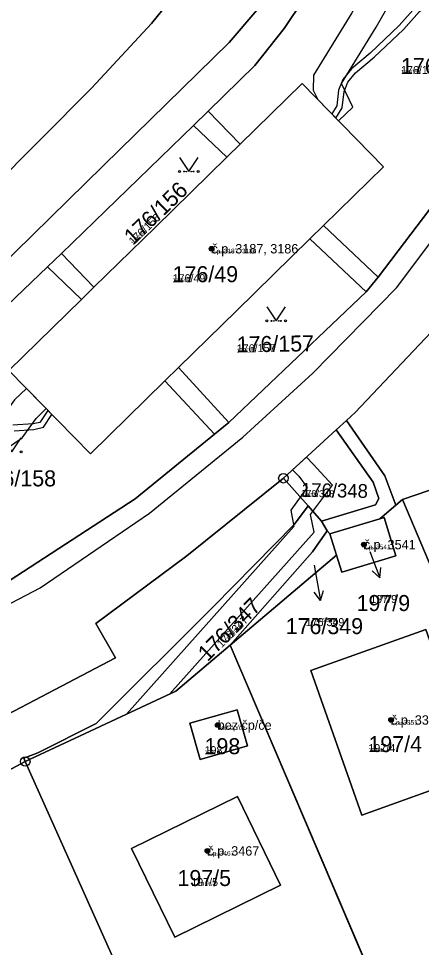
# Model space of a CAD drawing. Extents: x -759873 to -758487, y -975024 to -973516.
# Drawn here: x -759216.9 to -759174.1, y -974880.1 to -974781.5 of the extents above; entities that cross this region are included whole.
import ezdxf

# ---------------------------------------------------------------- set-up
doc = ezdxf.new("R2010")
doc.units = 0
for name, color, linetype in [('KAT_02_hranice parcel', 7, 'Continuous'), ('KAT_03_1000_st čísla parcelní', 7, 'Continuous'), ('KAT_03_1000_čísla parcelní', 7, 'Continuous'), ('KAT_03_1000_čísla popisná', 7, 'Continuous'), ('KAT_03_250_st čísla parcelní', 7, 'Continuous'), ('KAT_03_250_čísla parcelní', 7, 'Continuous'), ('KAT_03_250_čísla popisná', 7, 'Continuous'), ('KAT_03_500_st čísla parcelní', 7, 'Continuous'), ('KAT_03_500_čísla parcelní', 7, 'Continuous'), ('KAT_03_500_čísla popisná', 7, 'Continuous'), ('KAT_04_vnitřní kresba', 7, 'Continuous'), ('KAT_05_1000_značky kultur', 7, 'Continuous'), ('KAT_05_250_značky kultur', 7, 'Continuous'), ('KAT_05_500_značky kultur', 7, 'Continuous'), ('KAT_07_1000_značky budov', 7, 'Continuous'), ('KAT_07_250_značky budov', 7, 'Continuous'), ('KAT_07_500_značky budov', 7, 'Continuous'), ('KAT_10_věcná břemena', 7, 'Continuous'), ('KAT_11_značky bodu BP', 7, 'Continuous'), ('KAT_12_pomocná šipka', 7, 'Continuous'), ('KAT_14_plocha_budovy', 7, 'Continuous'), ('KAT_14_plocha_pozemek', 7, 'Continuous')]:
    doc.layers.add(name, color=color, linetype=linetype)

msp = doc.modelspace()

# ---------------------------------------------------------------- linework, layer by layer
at = {"layer": 'KAT_02_hranice parcel'}
for p, q in [((-759196.78, -974791.27), (-759198.31, -974792.79)), ((-759198.31, -974792.79), (-759212.35, -974806.39)), ((-759212.35, -974806.39), (-759213.82, -974807.81)), ((-759179.98, -974810.45), (-759178.71, -974808.89)), ((-759194.56, -974824.34), (-759179.98, -974810.45)), ((-759148.15, -974822.94), (-759176.11, -974832.51)), ((-759196.1, -974825.59), (-759194.56, -974824.34)), ((-759183.17, -974825.13), (-759182.08, -974824.14)), ((-759188.78, -974830.26), (-759183.17, -974825.13)), ((-759186.16, -974833.19), (-759188.78, -974830.26)), ((-759184.73, -974834.81), (-759186.16, -974833.19)), ((-759176.83, -974833.12), (-759178.53, -974834.55)), ((-759176.11, -974832.51), (-759176.83, -974833.12)), ((-759159.23, -974872.41), (-759176.11, -974832.51)), ((-759183.12, -974838.42), (-759194.44, -974847.98)), ((-759167.42, -974911.17), (-759194.44, -974847.98)), ((-759216.19, -974860.33), (-759226.6, -974865.92)), ((-759189.72, -974919.43), (-759216.19, -974860.33))]:
    msp.add_line(p, q, dxfattribs=at)
for points in [[(-759182.08, -974824.14), (-759181.15, -974823.29), (-759171.83, -974813.43), (-759165.02, -974804.41), (-759157.43, -974793.66), (-759153.11, -974796.03), (-759143.25, -974777.05), (-759139.01, -974766.6), (-759133.15, -974749.42), (-759137.89, -974748.23), (-759137.17, -974743.17), (-759136.73, -974730.48), (-759139.87, -974717.29), (-759146.64, -974706.25), (-759155.94, -974697.62), (-759168.19, -974691.87), (-759181.09, -974689.78), (-759191.31, -974690.97), (-759198.55, -974692.98), (-759199.06, -974691.99)], [(-759175.88, -974728.64), (-759173.57, -974730.28), (-759172.68, -974733.37), (-759174.3, -974738.51), (-759183.54, -974767.8), (-759185.24, -974771.49), (-759191.6, -974780.57), (-759194.54, -974783.98), (-759207.89, -974797.06), (-759222.97, -974811.82), (-759230.41, -974817.24), (-759237.61, -974821.2), (-759271.85, -974835.17), (-759280.57, -974837.54)], [(-759183.19, -974736.35), (-759176.58, -974737.4), (-759182.07, -974749.11), (-759190.12, -974766.32), (-759202.77, -974781.98), (-759209.13, -974788.81), (-759225.44, -974805.2), (-759239.06, -974815.12), (-759245.96, -974818.65), (-759258.28, -974823.9), (-759278.94, -974832.86), (-759280.49, -974821.62), (-759282.67, -974805.49), (-759285.3, -974797.52), (-759288.93, -974786.59), (-759266.24, -974774.27)], [(-759179.16, -974764.89), (-759180.75, -974769.83), (-759182.55, -974773.33), (-759188.7, -974782.52), (-759191.81, -974786.42), (-759196.78, -974791.27)], [(-759178.71, -974808.89), (-759171.77, -974799.76), (-759171.33, -974799.09), (-759163.17, -974786.79), (-759155.8, -974773.02)], [(-759178.71, -974808.89), (-759184.5, -974803.41), (-759178.14, -974797.19), (-759186.79, -974788.35), (-759193.36, -974794.78), (-759196.78, -974791.27)], [(-759198.31, -974792.79), (-759194.8, -974796.18), (-759202.36, -974803.59), (-759208.9, -974809.98), (-759212.35, -974806.39)], [(-759194.56, -974824.34), (-759199.92, -974818.5), (-759193.72, -974812.43), (-759185.95, -974804.84), (-759179.98, -974810.45)], [(-759213.82, -974807.81), (-759221.49, -974815.09), (-759223.9, -974816.9), (-759224.76, -974817.42), (-759235.96, -974824.17), (-759240.73, -974826.19)], [(-759213.82, -974807.81), (-759210.23, -974811.29), (-759217.93, -974818.82), (-759209.28, -974827.66), (-759201.37, -974819.92), (-759196.1, -974825.59)], [(-759182.08, -974824.14), (-759177.99, -974830.01), (-759176.83, -974833.12)], [(-759184.73, -974834.81), (-759179, -974833.07), (-759178.65, -974832.39), (-759179.25, -974830.66), (-759183.17, -974825.13)], [(-759231.42, -974847.97), (-759219.46, -974842.13), (-759218.62, -974841.59), (-759204.52, -974832.44), (-759196.1, -974825.59)], [(-759339.46, -974882.78), (-759339.8, -974881.64), (-759332.95, -974877.29), (-759323.1, -974873.6), (-759309.63, -974871.79), (-759306.19, -974871.77), (-759306.31, -974877.26), (-759289.39, -974877.59), (-759275.76, -974876.39), (-759260.46, -974873.03), (-759249.2, -974869.3), (-759236.4, -974863.83), (-759220.29, -974856.48), (-759206.61, -974849.33), (-759208.71, -974845.67), (-759199.03, -974838.5), (-759188.78, -974830.26)], [(-759216.19, -974860.33), (-759216.36, -974859.96), (-759214.86, -974859.41), (-759208.68, -974856.28), (-759196.21, -974843.87), (-759187.6, -974835.12), (-759186.16, -974833.19)], [(-759194.44, -974847.98), (-759185.69, -974838.07), (-759184.13, -974835.84), (-759184.73, -974834.81)], [(-759183.12, -974838.42), (-759183.83, -974836.16), (-759178.53, -974834.55)], [(-759178.53, -974834.55), (-759178.07, -974834.41), (-759176.83, -974838.48), (-759182.55, -974840.22), (-759183.12, -974838.42)], [(-759180.46, -974866.01), (-759185.86, -974850.67), (-759173.66, -974846.32), (-759168.24, -974861.65), (-759180.46, -974866.01)], [(-759194.44, -974847.98), (-759200.21, -974852.85), (-759216.19, -974860.33)], [(-759193.67, -974854.83), (-759192.58, -974858.68), (-759197.63, -974860.12), (-759198.72, -974856.27), (-759193.67, -974854.83)], [(-759189.07, -974873.46), (-759200.29, -974878.98), (-759204.91, -974869.57), (-759193.66, -974864.04), (-759189.07, -974873.46)]]:
    msp.add_lwpolyline(points, dxfattribs=at)
at = {"layer": 'KAT_03_1000_čísla popisná'}
for centre in [(-759196.41, -974805.89), (-759180.23, -974837.3), (-759177.34, -974855.92), (-759195.75, -974856.46), (-759196.84, -974869.82)]:
    msp.add_circle(centre, 0.25, dxfattribs=at)
at = {"layer": 'KAT_03_250_čísla popisná'}
for centre in [(-759196.41, -974805.89), (-759180.23, -974837.3), (-759177.34, -974855.92), (-759195.75, -974856.46), (-759196.84, -974869.82)]:
    msp.add_circle(centre, 0.0625, dxfattribs=at)
at = {"layer": 'KAT_03_500_čísla popisná'}
for centre in [(-759196.41, -974805.89), (-759180.23, -974837.3), (-759177.34, -974855.92), (-759195.75, -974856.46), (-759196.84, -974869.82)]:
    msp.add_circle(centre, 0.125, dxfattribs=at)
at = {"layer": 'KAT_04_vnitřní kresba'}
for p, q in [((-759194.8, -974796.18), (-759193.36, -974794.78)), ((-759176.75, -974810.03), (-759170.02, -974801.04)), ((-759185.95, -974804.84), (-759184.5, -974803.41)), ((-759210.23, -974811.29), (-759208.9, -974809.98)), ((-759185.64, -974819.1), (-759176.75, -974810.03)), ((-759201.37, -974819.92), (-759199.92, -974818.5)), ((-759193.1, -974825.91), (-759185.64, -974819.1)), ((-759202.98, -974833.95), (-759193.1, -974825.91)), ((-759214.6, -974841.89), (-759202.98, -974833.95)), ((-759225.26, -974847.47), (-759214.6, -974841.89))]:
    msp.add_line(p, q, dxfattribs=at)
at = {"layer": 'KAT_05_1000_značky kultur'}
for points in [[(-759199.82, -974796.189), (-759198.82, -974797.69), (-759197.82, -974796.189)], [(-759190.54, -974812.049), (-759189.54, -974813.55), (-759188.54, -974812.049)], [(-759218.63, -974825.949), (-759217.63, -974827.45), (-759216.63, -974825.949)]]:
    msp.add_lwpolyline(points, dxfattribs=at)
for centre in [(-759199.82, -974797.689), (-759197.82, -974797.689), (-759190.54, -974813.549), (-759188.54, -974813.549), (-759216.63, -974827.449)]:
    msp.add_circle(centre, 0.1, dxfattribs=at)
at = {"layer": 'KAT_05_250_značky kultur'}
for points in [[(-759199.07, -974797.315), (-759198.82, -974797.69), (-759198.57, -974797.315)], [(-759189.79, -974813.175), (-759189.54, -974813.55), (-759189.29, -974813.175)]]:
    msp.add_lwpolyline(points, dxfattribs=at)
for centre in [(-759199.07, -974797.69), (-759198.57, -974797.69), (-759189.79, -974813.55), (-759189.29, -974813.55)]:
    msp.add_circle(centre, 0.025, dxfattribs=at)
at = {"layer": 'KAT_05_500_značky kultur'}
for points in [[(-759199.32, -974796.939), (-759198.82, -974797.69), (-759198.32, -974796.939)], [(-759190.04, -974812.799), (-759189.54, -974813.55), (-759189.04, -974812.799)]]:
    msp.add_lwpolyline(points, dxfattribs=at)
for centre in [(-759199.32, -974797.69), (-759198.32, -974797.69), (-759190.04, -974813.55), (-759189.04, -974813.55)]:
    msp.add_circle(centre, 0.05, dxfattribs=at)
at = {"layer": 'KAT_07_1000_značky budov'}
for centre in [(-759196.417, -974805.889), (-759180.237, -974837.299), (-759177.347, -974855.919), (-759195.757, -974856.459), (-759196.847, -974869.819)]:
    msp.add_circle(centre, 0.175, dxfattribs=at)
at = {"layer": 'KAT_07_250_značky budov'}
for centre in [(-759196.412, -974805.89), (-759180.232, -974837.3), (-759177.342, -974855.92), (-759195.752, -974856.46), (-759196.842, -974869.82)]:
    msp.add_circle(centre, 0.0437, dxfattribs=at)
at = {"layer": 'KAT_07_500_značky budov'}
for centre in [(-759196.413, -974805.89), (-759180.233, -974837.3), (-759177.343, -974855.92), (-759195.753, -974856.46), (-759196.843, -974869.82)]:
    msp.add_circle(centre, 0.0875, dxfattribs=at)
at = {"layer": 'KAT_10_věcná břemena'}
for points in [[(-759176.47, -974778.05), (-759176.17, -974777.21), (-759177.93, -974776.57), (-759178.99, -974776.19), (-759179.21, -974776.79), (-759181.51, -974780.84), (-759185.57, -974787.45), (-759185.61, -974789.04), (-759185.12, -974790.05), (-759182.92, -974792.3), (-759181.4, -974790.87), (-759182.59, -974788.33), (-759178.93, -974782.36)], [(-759172.3, -974778.6), (-759172.87, -974778.39), (-759173.23, -974778.96), (-759173.78, -974779.45), (-759174.74, -974780.26), (-759176.47, -974782.18), (-759179.55, -974785.11), (-759181.53, -974786.79), (-759182.46, -974787.92), (-759182.91, -974789.05), (-759183.11, -974790.72), (-759183.64, -974791.57), (-759183.2, -974792.02), (-759182.53, -974790.92), (-759182.33, -974789.19), (-759181.94, -974788.22), (-759181.11, -974787.21), (-759179.15, -974785.55), (-759176.03, -974782.6), (-759174.32, -974780.7), (-759173.38, -974779.91), (-759172.77, -974779.36)], [(-759215.04, -974823.9), (-759213.97, -974822.86), (-759216.07, -974820.72), (-759217.32, -974821.94), (-759218.63, -974823.77), (-759219.32, -974824.24), (-759224.54, -974825.51), (-759230.32, -974827.78), (-759229.18, -974830.56), (-759223.64, -974828.37), (-759218.08, -974827.02), (-759216.51, -974825.95)], [(-759182.08, -974824.14), (-759183.17, -974825.13), (-759179.25, -974830.66), (-759178.65, -974832.39), (-759179, -974833.07), (-759184.73, -974834.81), (-759184.13, -974835.84), (-759183.83, -974836.16), (-759178.53, -974834.55), (-759176.83, -974833.12), (-759177.99, -974830.01)], [(-759183.56, -974830.98), (-759185.6, -974828.77), (-759186.31, -974828), (-759187.79, -974829.35), (-759187.14, -974830.05), (-759186.25, -974831.25), (-759188, -974833.64), (-759187.67, -974835.39), (-759205.45, -974855.3), (-759200.84, -974853.14), (-759185.51, -974835.99), (-759185.88, -974834.12)]]:
    msp.add_lwpolyline(points, close=True, dxfattribs=at)
msp.add_lwpolyline([(-759217.37, -974825.22), (-759215.27, -974825.09), (-759214.27, -974824.85), (-759213.37, -974823.48), (-759213.8, -974823.05), (-759214.63, -974824.33), (-759215.35, -974824.49), (-759217.51, -974824.62)], dxfattribs=at)
at = {"layer": 'KAT_11_značky bodu BP'}
for centre, radius in [((-759188.78, -974830.26), 0.5), ((-759188.78, -974830.26), 0.0303), ((-759216.19, -974860.33), 0.5), ((-759216.19, -974860.33), 0.0303)]:
    msp.add_circle(centre, radius, dxfattribs=at)
at = {"layer": 'KAT_12_pomocná šipka'}
for p, q in [((-759179.6, -974838.03), (-759178.525, -974840.832)), ((-759185.51, -974839.48), (-759185.36, -974840.28)), ((-759178.525, -974840.832), (-759179.351, -974840.076)), ((-759178.525, -974840.832), (-759178.416, -974839.717)), ((-759185.36, -974840.28), (-759184.839, -974843.235)), ((-759184.839, -974843.235), (-759185.506, -974842.336)), ((-759184.839, -974843.235), (-759184.52, -974842.162))]:
    msp.add_line(p, q, dxfattribs=at)
at = {"layer": 'KAT_14_plocha_budovy'}
for points in [[(-759208.9, -974809.98), (-759210.23, -974811.29), (-759217.93, -974818.82), (-759209.28, -974827.66), (-759201.37, -974819.92), (-759199.92, -974818.5), (-759193.72, -974812.43), (-759185.95, -974804.84), (-759184.5, -974803.41), (-759178.14, -974797.19), (-759186.79, -974788.35), (-759193.36, -974794.78), (-759194.8, -974796.18), (-759202.36, -974803.59)], [(-759183.83, -974836.16), (-759183.12, -974838.42), (-759182.55, -974840.22), (-759176.83, -974838.48), (-759178.07, -974834.41), (-759178.53, -974834.55)], [(-759185.86, -974850.67), (-759180.46, -974866.01), (-759168.24, -974861.65), (-759173.66, -974846.32)], [(-759193.67, -974854.83), (-759198.72, -974856.27), (-759197.63, -974860.12), (-759192.58, -974858.68)], [(-759193.66, -974864.04), (-759204.91, -974869.57), (-759200.29, -974878.98), (-759189.07, -974873.46)]]:
    msp.add_lwpolyline(points, close=True, dxfattribs=at)
at = {"layer": 'KAT_14_plocha_pozemek'}
for points in [[(-759143.25, -974777.05), (-759153.11, -974796.03), (-759157.43, -974793.66), (-759165.02, -974804.41), (-759171.83, -974813.43), (-759181.15, -974823.29), (-759182.08, -974824.14), (-759177.99, -974830.01), (-759176.83, -974833.12), (-759176.11, -974832.51), (-759148.15, -974822.94), (-759101.42, -974795.61), (-759103.79, -974793.94), (-759111.25, -974781.7), (-759124.4, -974742.82)], [(-759190.12, -974766.32), (-759202.77, -974781.98), (-759209.13, -974788.81), (-759225.44, -974805.2), (-759239.06, -974815.12), (-759245.96, -974818.65), (-759258.28, -974823.9), (-759278.94, -974832.86), (-759280.49, -974821.62), (-759282.67, -974805.49), (-759285.3, -974797.52), (-759288.93, -974786.59), (-759266.24, -974774.27)], [(-759266.24, -974774.27), (-759288.93, -974786.59), (-759285.3, -974797.52), (-759282.67, -974805.49), (-759280.49, -974821.62), (-759278.94, -974832.86), (-759258.28, -974823.9), (-759245.96, -974818.65), (-759239.06, -974815.12), (-759225.44, -974805.2), (-759209.13, -974788.81), (-759202.77, -974781.98), (-759190.12, -974766.32)], [(-759298.96, -974841.08), (-759296.85, -974841.17), (-759289.12, -974841.49), (-759283.04, -974841.37), (-759281.44, -974841.14), (-759270.88, -974838.48), (-759262.91, -974835.25), (-759260.85, -974834.41), (-759242.72, -974826.98), (-759240.73, -974826.19), (-759235.96, -974824.17), (-759224.76, -974817.42), (-759223.9, -974816.9), (-759221.49, -974815.09), (-759213.82, -974807.81), (-759212.35, -974806.39), (-759198.31, -974792.79), (-759196.78, -974791.27), (-759191.81, -974786.42), (-759188.7, -974782.52), (-759182.55, -974773.33)], [(-759282.01, -974779.76), (-759293.14, -974783.84), (-759287, -974798.76), (-759284.82, -974806.4), (-759282.72, -974821.86), (-759280.57, -974837.54), (-759271.85, -974835.17), (-759237.61, -974821.2), (-759230.41, -974817.24), (-759222.97, -974811.82), (-759207.89, -974797.06), (-759194.54, -974783.98), (-759191.6, -974780.57)], [(-759191.6, -974780.57), (-759194.54, -974783.98), (-759207.89, -974797.06), (-759222.97, -974811.82), (-759230.41, -974817.24), (-759237.61, -974821.2), (-759271.85, -974835.17), (-759280.57, -974837.54), (-759281.55, -974837.72), (-759288.97, -974837.7), (-759308.21, -974836.87)], [(-759171.77, -974799.76), (-759178.71, -974808.89), (-759179.98, -974810.45), (-759194.56, -974824.34), (-759196.1, -974825.59), (-759204.52, -974832.44), (-759218.62, -974841.59), (-759219.46, -974842.13), (-759231.42, -974847.97), (-759233.35, -974848.89), (-759251.38, -974856.67), (-759253.29, -974857.47), (-759264.57, -974861.27), (-759277.27, -974863.6), (-759278.8, -974863.8), (-759286.09, -974864.19), (-759286.94, -974864.24), (-759289.42, -974864.28), (-759298.85, -974863.88), (-759300.86, -974863.82)], [(-759306.31, -974877.26), (-759289.39, -974877.59), (-759275.76, -974876.39), (-759260.46, -974873.03), (-759249.2, -974869.3), (-759236.4, -974863.83), (-759220.29, -974856.48), (-759206.61, -974849.33), (-759208.71, -974845.67), (-759199.03, -974838.5), (-759188.78, -974830.26), (-759183.17, -974825.13), (-759182.08, -974824.14), (-759181.15, -974823.29), (-759171.83, -974813.43)], [(-759309.62, -974881.37), (-759294.63, -974881.97), (-759273.68, -974881.15), (-759273.27, -974884.11), (-759238.51, -974872.32), (-759226.6, -974865.92), (-759216.19, -974860.33), (-759216.36, -974859.96), (-759214.86, -974859.41), (-759208.68, -974856.28), (-759196.21, -974843.87), (-759187.6, -974835.12), (-759186.16, -974833.19), (-759188.78, -974830.26), (-759199.03, -974838.5), (-759208.71, -974845.67), (-759206.61, -974849.33), (-759220.29, -974856.48), (-759236.4, -974863.83), (-759249.2, -974869.3), (-759260.46, -974873.03), (-759275.76, -974876.39), (-759289.39, -974877.59), (-759306.31, -974877.26)]]:
    msp.add_lwpolyline(points, dxfattribs=at)
for points in [[(-759171.77, -974799.76), (-759171.33, -974799.09), (-759163.17, -974786.79), (-759155.8, -974773.02), (-759162.58, -974770.43), (-759166.31, -974780.76), (-759177.93, -974776.57), (-759174.26, -974766.42), (-759179.16, -974764.89), (-759180.75, -974769.83), (-759182.55, -974773.33), (-759188.7, -974782.52), (-759191.81, -974786.42), (-759196.78, -974791.27), (-759193.36, -974794.78), (-759186.79, -974788.35), (-759178.14, -974797.19), (-759184.5, -974803.41), (-759178.71, -974808.89)], [(-759185.95, -974804.84), (-759179.98, -974810.45), (-759178.71, -974808.89), (-759184.5, -974803.41), (-759178.14, -974797.19), (-759186.79, -974788.35), (-759193.36, -974794.78), (-759196.78, -974791.27), (-759198.31, -974792.79), (-759194.8, -974796.18), (-759202.36, -974803.59), (-759208.9, -974809.98), (-759212.35, -974806.39), (-759213.82, -974807.81), (-759210.23, -974811.29), (-759217.93, -974818.82), (-759209.28, -974827.66), (-759201.37, -974819.92), (-759196.1, -974825.59), (-759194.56, -974824.34), (-759199.92, -974818.5), (-759193.72, -974812.43)], [(-759198.31, -974792.79), (-759212.35, -974806.39), (-759208.9, -974809.98), (-759202.36, -974803.59), (-759194.8, -974796.18)], [(-759179.98, -974810.45), (-759185.95, -974804.84), (-759193.72, -974812.43), (-759199.92, -974818.5), (-759194.56, -974824.34)], [(-759204.52, -974832.44), (-759196.1, -974825.59), (-759201.37, -974819.92), (-759209.28, -974827.66), (-759217.93, -974818.82), (-759210.23, -974811.29), (-759213.82, -974807.81), (-759221.49, -974815.09), (-759223.9, -974816.9), (-759224.76, -974817.42), (-759235.96, -974824.17), (-759240.73, -974826.19), (-759238.94, -974830.91), (-759230.46, -974827.44), (-759225.78, -974838.87), (-759234, -974842.24), (-759231.42, -974847.97), (-759219.46, -974842.13), (-759218.62, -974841.59)], [(-759145.06, -974828.98), (-759148.15, -974822.94), (-759176.11, -974832.51), (-759159.23, -974872.41), (-759128.83, -974862.14)], [(-759183.12, -974838.42), (-759183.83, -974836.16), (-759178.53, -974834.55), (-759176.83, -974833.12), (-759177.99, -974830.01), (-759182.08, -974824.14), (-759183.17, -974825.13), (-759179.25, -974830.66), (-759178.65, -974832.39), (-759179, -974833.07), (-759184.73, -974834.81), (-759184.13, -974835.84), (-759185.69, -974838.07), (-759194.44, -974847.98)], [(-759178.65, -974832.39), (-759179.25, -974830.66), (-759183.17, -974825.13), (-759188.78, -974830.26), (-759186.16, -974833.19), (-759184.73, -974834.81), (-759179, -974833.07)], [(-759194.44, -974847.98), (-759185.69, -974838.07), (-759184.13, -974835.84), (-759184.73, -974834.81), (-759186.16, -974833.19), (-759187.6, -974835.12), (-759196.21, -974843.87), (-759208.68, -974856.28), (-759214.86, -974859.41), (-759216.36, -974859.96), (-759216.19, -974860.33), (-759200.21, -974852.85)], [(-759178.07, -974834.41), (-759176.83, -974838.48), (-759182.55, -974840.22), (-759183.12, -974838.42), (-759194.44, -974847.98), (-759167.42, -974911.17), (-759145.92, -974903.21), (-759159.23, -974872.41), (-759176.11, -974832.51), (-759176.83, -974833.12), (-759178.53, -974834.55)], [(-759183.12, -974838.42), (-759182.55, -974840.22), (-759176.83, -974838.48), (-759178.07, -974834.41), (-759178.53, -974834.55), (-759183.83, -974836.16)], [(-759180.46, -974866.01), (-759185.86, -974850.67), (-759173.66, -974846.32), (-759168.24, -974861.65)], [(-759180.46, -974866.01), (-759168.24, -974861.65), (-759173.66, -974846.32), (-759185.86, -974850.67)], [(-759194.44, -974847.98), (-759200.21, -974852.85), (-759216.19, -974860.33), (-759189.72, -974919.43), (-759167.42, -974911.17)], [(-759193.67, -974854.83), (-759198.72, -974856.27), (-759197.63, -974860.12), (-759192.58, -974858.68)], [(-759193.67, -974854.83), (-759192.58, -974858.68), (-759197.63, -974860.12), (-759198.72, -974856.27)], [(-759216.19, -974860.33), (-759226.6, -974865.92), (-759217.66, -974889.98), (-759216.48, -974893.8), (-759203.97, -974928.37), (-759188.86, -974921.74), (-759189.72, -974919.43)], [(-759189.07, -974873.46), (-759200.29, -974878.98), (-759204.91, -974869.57), (-759193.66, -974864.04)], [(-759189.07, -974873.46), (-759193.66, -974864.04), (-759204.91, -974869.57), (-759200.29, -974878.98)]]:
    msp.add_lwpolyline(points, close=True, dxfattribs=at)

# ---------------------------------------------------------------- texts
at = {"layer": 'KAT_03_1000_st čísla parcelní'}
for s, p in [('176/49', (-759200.54, -974809.44)), ('197/9', (-759181.003, -974844.353)), ('198', (-759197.15, -974859.549)), ('197/4', (-759179.74, -974859.33)), ('197/5', (-759200.023, -974873.549))]:
    msp.add_text(s, height=1.7, dxfattribs=at).set_placement(p)
at = {"layer": 'KAT_03_1000_čísla parcelní'}
for s, p in [('176/155', (-759176.28, -974787.34)), ('176/158', (-759221.14, -974831.12)), ('176/349', (-759188.528, -974846.803))]:
    msp.add_text(s, height=1.7, dxfattribs=at).set_placement(p)
for s, height, rotation, p in [('176/156', 1.7, 44, (-759204.709, -974805.551)), ('176/157', 1.7, 1, (-759193.725, -974816.909)), ('176/348', 1.469, 359, (-759186.912, -974832.224)), ('176/347', 1.7, 45, (-759196.832, -974849.804))]:
    msp.add_text(s, height=height, rotation=rotation, dxfattribs=at).set_placement(p)
at = {"layer": 'KAT_03_1000_čísla popisná'}
for s, p in [('č.p. 3187, 3186', (-759196.41, -974806.39)), ('č.p. 3541', (-759180.23, -974837.8)), ('bez čp/če', (-759195.75, -974856.96)), ('č.p. 3351', (-759177.34, -974856.42)), ('č.p. 3467', (-759196.84, -974870.32))]:
    msp.add_text(s, height=1, dxfattribs=at).set_placement(p)
at = {"layer": 'KAT_03_250_st čísla parcelní'}
for s, p in [('176/49', (-759200.54, -974809.44)), ('197/9', (-759178.815, -974843.078)), ('197/4', (-759179.74, -974859.33)), ('198', (-759197.15, -974859.549)), ('197/5', (-759197.831, -974873.549))]:
    msp.add_text(s, height=0.425, dxfattribs=at).set_placement(p)
at = {"layer": 'KAT_03_250_čísla parcelní'}
for s, p in [('176/155', (-759176.28, -974787.34)), ('176/349', (-759185.349, -974845.528))]:
    msp.add_text(s, height=0.425, dxfattribs=at).set_placement(p)
for s, height, rotation, p in [('176/156', 0.425, 44, (-759204.709, -974805.551)), ('176/157', 0.425, 1, (-759193.725, -974816.909)), ('176/348', 0.3672, 359, (-759186.912, -974832.224)), ('176/347', 0.425, 45, (-759194.585, -974847.557))]:
    msp.add_text(s, height=height, rotation=rotation, dxfattribs=at).set_placement(p)
at = {"layer": 'KAT_03_250_čísla popisná'}
for s, p in [('č.p. 3187, 3186', (-759196.41, -974806.39)), ('č.p. 3541', (-759180.23, -974837.8)), ('bez čp/če', (-759195.75, -974856.96)), ('č.p. 3351', (-759177.34, -974856.42)), ('č.p. 3467', (-759196.84, -974870.32))]:
    msp.add_text(s, height=0.25, dxfattribs=at).set_placement(p)
at = {"layer": 'KAT_03_500_st čísla parcelní'}
for s, p in [('176/49', (-759200.54, -974809.44)), ('197/9', (-759179.544, -974843.503)), ('198', (-759197.15, -974859.549)), ('197/4', (-759179.74, -974859.33)), ('197/5', (-759198.561, -974873.549))]:
    msp.add_text(s, height=0.85, dxfattribs=at).set_placement(p)
at = {"layer": 'KAT_03_500_čísla parcelní'}
for s, p in [('176/155', (-759176.28, -974787.34)), ('176/349', (-759186.409, -974845.953))]:
    msp.add_text(s, height=0.85, dxfattribs=at).set_placement(p)
for s, height, rotation, p in [('176/156', 0.85, 44, (-759204.709, -974805.551)), ('176/157', 0.85, 1, (-759193.725, -974816.909)), ('176/348', 0.7345, 359, (-759186.912, -974832.224)), ('176/347', 0.85, 45, (-759195.334, -974848.306))]:
    msp.add_text(s, height=height, rotation=rotation, dxfattribs=at).set_placement(p)
at = {"layer": 'KAT_03_500_čísla popisná'}
for s, p in [('č.p. 3187, 3186', (-759196.41, -974806.39)), ('č.p. 3541', (-759180.23, -974837.8)), ('č.p. 3351', (-759177.34, -974856.42)), ('bez čp/če', (-759195.75, -974856.96)), ('č.p. 3467', (-759196.84, -974870.32))]:
    msp.add_text(s, height=0.5, dxfattribs=at).set_placement(p)

doc.saveas('drawing.dxf')
